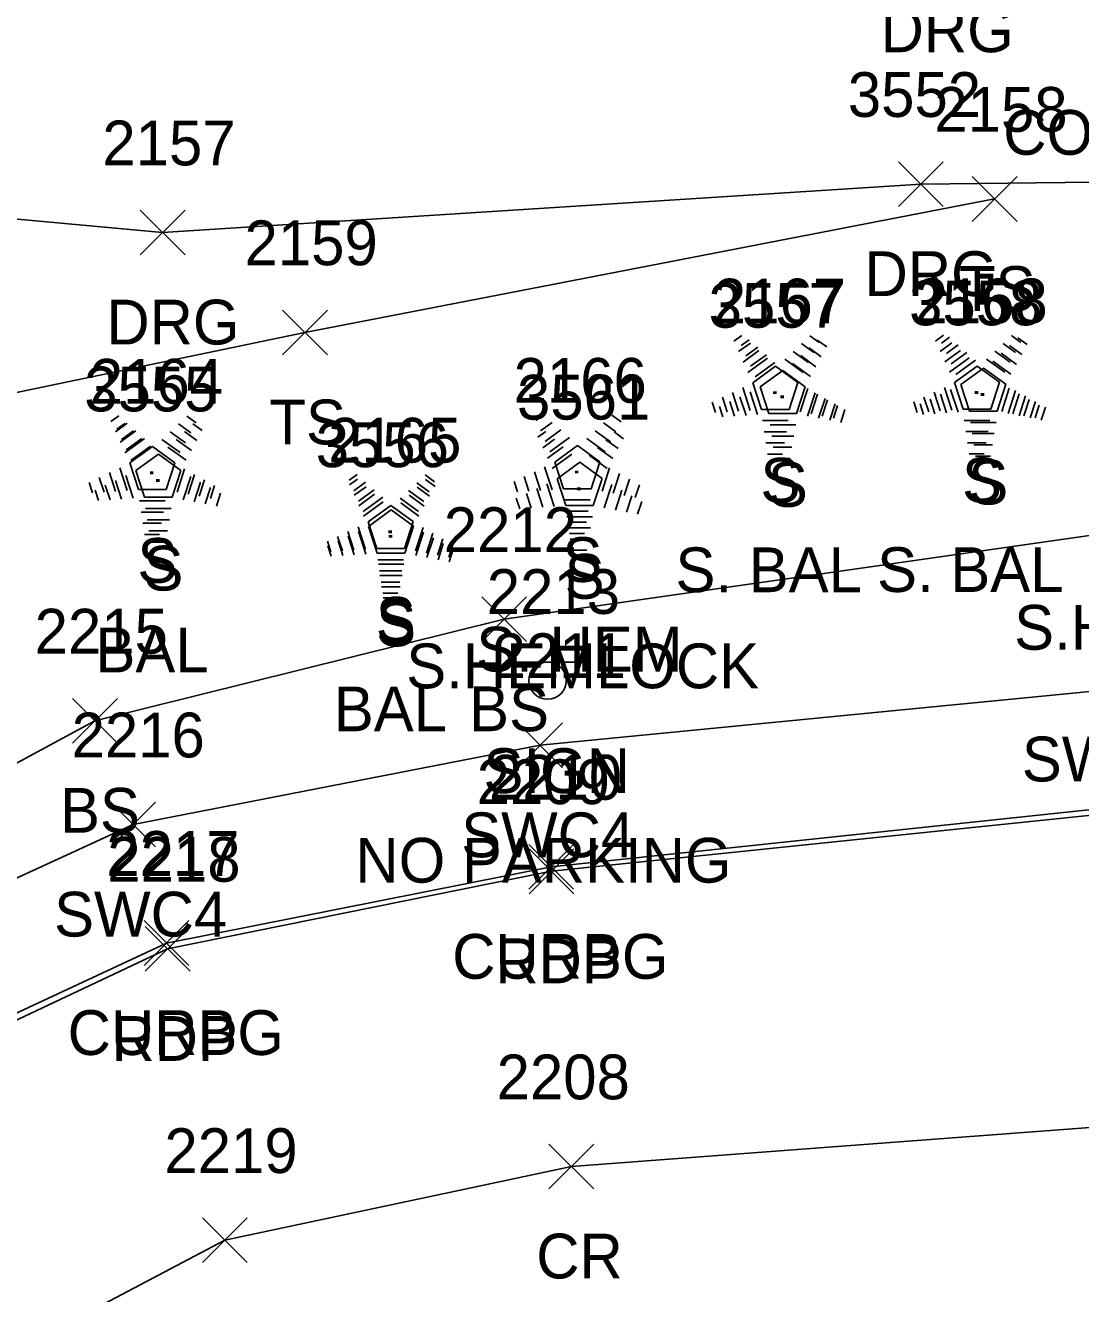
# Model space of a CAD drawing. Extents: x 49137 to 50946, y 9590 to 10709.
# Drawn here: x 50015.9 to 50063, y 10129.9 to 10186.5 of the extents above; entities that cross this region are included whole.
import ezdxf

# ---------------------------------------------------------------- set-up
doc = ezdxf.new("R2010")
doc.units = 0
for name, color, linetype in [('L_A', 7, 'Continuous'), ('L_C', 7, 'Continuous'), ('L_I', 7, 'Continuous'), ('L_TIC', 7, 'Continuous'), ('LELB', 7, 'Continuous'), ('LTC', 7, 'Continuous'), ('P_A', 7, 'Continuous'), ('P_I', 7, 'Continuous'), ('P_TIC', 7, 'Continuous'), ('PET', 7, 'Continuous'), ('PRC', 7, 'Continuous'), ('R_A', 7, 'Continuous'), ('R_I', 7, 'Continuous'), ('R_TIC', 7, 'Continuous'), ('RC', 7, 'Continuous'), ('RDG', 7, 'Continuous'), ('RSW', 7, 'Continuous'), ('S_A', 7, 'Continuous'), ('S_C', 7, 'Continuous'), ('S_I', 7, 'Continuous'), ('SSGN', 7, 'Continuous')]:
    doc.layers.add(name, color=color, linetype=linetype)

msp = doc.modelspace()

# ---------------------------------------------------------------- linework, layer by layer
at = {"layer": 'L_TIC'}
for points in [[(50058.207, 10177.77), (50060.207, 10179.77)], [(50060.207, 10177.77), (50058.207, 10179.77)], [(50027.413, 10171.811), (50029.413, 10173.811)], [(50029.413, 10171.811), (50027.413, 10173.811)], [(50036.302, 10159), (50038.302, 10161)], [(50038.302, 10159), (50036.302, 10161)], [(50018.035, 10154.468), (50020.035, 10156.468)], [(50020.035, 10154.468), (50018.035, 10156.468)]]:
    msp.add_lwpolyline(points, dxfattribs=at)
at = {"layer": 'LELB'}
for points in [[(50059.207, 10178.77), (50028.413, 10172.811), (50009.729, 10168.921), (49990.014, 10158.531), (49982.121, 10132.61), (49968.204, 10108.513), (49962.139, 10093.516), (49959.115, 10077.066), (49958.099, 10070.421), (49954.983, 10070.006), (49949.237, 10070.265), (49946.938, 10062.783)], [(50098.239, 10171.767), (50082.638, 10166.885), (50071.985, 10164.968), (50037.302, 10160), (50019.035, 10155.468), (49996.071, 10143.044), (49982.121, 10132.61), (49977.73, 10134.389), (49971.722, 10123.997), (49967.691, 10108.727), (49960.47, 10094.086), (49957.429, 10077.197), (49956.319, 10072.029), (49954.648, 10071.844), (49954.156, 10074.76), (49955.264, 10079.229)]]:
    msp.add_lwpolyline(points, dxfattribs=at)
at = {"layer": 'LTC'}
for p, q in [((50047.56, 10172.418), (50047.915, 10172.675)), ((50050.959, 10172.658), (50051.378, 10172.353)), ((50056.563, 10172.427), (50056.917, 10172.684)), ((50056.841, 10172.335), (50057.196, 10172.592)), ((50059.961, 10172.667), (50060.38, 10172.363)), ((50060.24, 10172.575), (50060.659, 10172.271)), ((50047.77, 10171.952), (50048.299, 10172.336)), ((50047.891, 10172.229), (50048.245, 10172.486)), ((50047.979, 10171.486), (50048.683, 10171.998)), ((50048.1, 10171.763), (50048.629, 10172.148)), ((50050.216, 10171.961), (50050.896, 10171.468)), ((50050.587, 10172.31), (50051.137, 10171.91)), ((50050.918, 10172.121), (50051.467, 10171.722)), ((50051.289, 10172.469), (50051.708, 10172.165)), ((50056.772, 10171.962), (50057.301, 10172.346)), ((50056.982, 10171.496), (50057.686, 10172.007)), ((50057.051, 10171.87), (50057.58, 10172.254)), ((50059.219, 10171.971), (50059.898, 10171.477)), ((50059.59, 10172.319), (50060.139, 10171.92)), ((50059.869, 10172.227), (50060.418, 10171.828)), ((50048.189, 10171.02), (50049.067, 10171.658)), ((50048.31, 10171.298), (50049.014, 10171.809)), ((50048.519, 10170.832), (50049.398, 10171.47)), ((50049.845, 10171.613), (50050.655, 10171.024)), ((50050.176, 10171.424), (50050.985, 10170.836)), ((50050.547, 10171.773), (50051.226, 10171.279)), ((50057.191, 10171.03), (50058.07, 10171.668)), ((50057.261, 10171.404), (50057.964, 10171.915)), ((50057.47, 10170.938), (50058.349, 10171.576)), ((50058.848, 10171.622), (50059.657, 10171.034)), ((50059.126, 10171.53), (50059.936, 10170.942)), ((50059.498, 10171.879), (50060.177, 10171.385)), ((50048.414, 10170.565), (50049.425, 10171.3)), ((50048.744, 10170.377), (50049.756, 10171.111)), ((50049.425, 10171.3), (50050.422, 10170.575)), ((50049.756, 10171.111), (50050.753, 10170.386)), ((50057.416, 10170.575), (50058.428, 10171.309)), ((50057.695, 10170.483), (50058.706, 10171.217)), ((50058.428, 10171.309), (50059.425, 10170.584)), ((50058.706, 10171.217), (50059.704, 10170.492)), ((50047.959, 10170.346), (50048.29, 10169.327)), ((50048.414, 10170.565), (50048.801, 10169.372)), ((50048.744, 10170.377), (50049.131, 10169.183)), ((50050.422, 10170.575), (50050.031, 10169.372)), ((50050.753, 10170.386), (50050.361, 10169.183)), ((50050.86, 10170.304), (50050.522, 10169.265)), ((50056.961, 10170.356), (50057.292, 10169.337)), ((50057.24, 10170.264), (50057.571, 10169.245)), ((50057.416, 10170.575), (50057.803, 10169.382)), ((50057.695, 10170.483), (50058.082, 10169.29)), ((50059.425, 10170.584), (50059.033, 10169.382)), ((50059.704, 10170.492), (50059.312, 10169.29)), ((50059.862, 10170.314), (50059.524, 10169.274)), ((50046.593, 10169.697), (50046.745, 10169.229)), ((50047.048, 10169.913), (50047.26, 10169.262)), ((50047.379, 10169.725), (50047.59, 10169.073)), ((50047.504, 10170.13), (50047.775, 10169.295)), ((50047.834, 10169.941), (50048.105, 10169.106)), ((50048.289, 10170.158), (50048.62, 10169.138)), ((50051.19, 10170.116), (50050.852, 10169.076)), ((50051.304, 10170.054), (50051.017, 10169.169)), ((50051.635, 10169.865), (50051.347, 10168.981)), ((50051.749, 10169.804), (50051.512, 10169.074)), ((50055.595, 10169.706), (50055.747, 10169.238)), ((50056.051, 10169.923), (50056.262, 10169.271)), ((50056.329, 10169.831), (50056.541, 10169.179)), ((50056.506, 10170.139), (50056.777, 10169.304)), ((50056.785, 10170.047), (50057.056, 10169.212)), ((50060.141, 10170.222), (50059.803, 10169.182)), ((50060.307, 10170.063), (50060.019, 10169.179)), ((50060.586, 10169.971), (50060.298, 10169.087)), ((50060.751, 10169.813), (50060.514, 10169.084)), ((50061.03, 10169.721), (50060.793, 10168.992)), ((50038.715, 10168.874), (50039.07, 10169.132)), ((50042.113, 10169.115), (50042.532, 10168.81)), ((50046.923, 10169.508), (50047.075, 10169.04)), ((50050.031, 10169.372), (50048.801, 10169.372)), ((50050.361, 10169.183), (50049.131, 10169.183)), ((50052.079, 10169.615), (50051.842, 10168.886)), ((50052.193, 10169.553), (50052.006, 10168.979)), ((50052.524, 10169.365), (50052.337, 10168.791)), ((50055.874, 10169.614), (50056.026, 10169.146)), ((50059.033, 10169.382), (50057.803, 10169.382)), ((50059.312, 10169.29), (50058.082, 10169.29)), ((50061.196, 10169.563), (50061.009, 10168.989)), ((50061.474, 10169.471), (50061.288, 10168.897)), ((50019.74, 10168.835), (50020.095, 10169.092)), ((50019.95, 10168.369), (50020.479, 10168.753)), ((50020.01, 10168.492), (50020.365, 10168.749)), ((50022.767, 10168.727), (50023.317, 10168.328)), ((50023.139, 10169.075), (50023.558, 10168.771)), ((50023.409, 10168.732), (50023.828, 10168.427)), ((50038.925, 10168.409), (50039.454, 10168.793)), ((50041.742, 10168.766), (50042.292, 10168.367)), ((50049.993, 10168.872), (50048.848, 10168.872)), ((50050.323, 10168.683), (50049.179, 10168.683)), ((50058.995, 10168.882), (50057.851, 10168.882)), ((50059.274, 10168.79), (50058.129, 10168.79)), ((50020.159, 10167.903), (50020.863, 10168.415)), ((50020.22, 10168.026), (50020.749, 10168.41)), ((50020.369, 10167.438), (50021.247, 10168.076)), ((50020.429, 10167.56), (50021.133, 10168.072)), ((50022.025, 10168.03), (50022.835, 10167.441)), ((50022.397, 10168.378), (50023.076, 10167.885)), ((50022.666, 10168.035), (50023.346, 10167.542)), ((50023.037, 10168.384), (50023.587, 10167.985)), ((50038.816, 10168.126), (50039.171, 10168.384)), ((50039.026, 10167.661), (50039.555, 10168.045)), ((50039.134, 10167.943), (50039.838, 10168.454)), ((50039.344, 10167.477), (50040.222, 10168.115)), ((50041, 10168.07), (50041.81, 10167.481)), ((50041.371, 10168.418), (50042.05, 10167.924)), ((50041.843, 10168.018), (50042.393, 10167.619)), ((50042.215, 10168.367), (50042.634, 10168.062)), ((50049.909, 10168.372), (50048.921, 10168.372)), ((50050.239, 10168.183), (50049.251, 10168.183)), ((50058.911, 10168.382), (50057.923, 10168.382)), ((50059.19, 10168.29), (50058.202, 10168.29)), ((50020.594, 10166.983), (50021.605, 10167.717)), ((50020.639, 10167.095), (50021.517, 10167.732)), ((50021.605, 10167.717), (50022.602, 10166.992)), ((50022.295, 10167.687), (50023.105, 10167.098)), ((50039.236, 10167.195), (50039.939, 10167.706)), ((50039.568, 10167.022), (50040.58, 10167.757)), ((50040.58, 10167.757), (50041.577, 10167.032)), ((50041.473, 10167.67), (50042.152, 10167.176)), ((50049.825, 10167.872), (50048.994, 10167.872)), ((50050.156, 10167.683), (50049.324, 10167.683)), ((50058.828, 10167.882), (50057.996, 10167.882)), ((50059.106, 10167.79), (50058.275, 10167.79)), ((50020.594, 10166.983), (50020.981, 10165.789)), ((50020.864, 10166.64), (50021.875, 10167.374)), ((50021.875, 10167.374), (50022.872, 10166.649)), ((50022.602, 10166.992), (50022.211, 10165.789)), ((50039.445, 10166.729), (50040.323, 10167.367)), ((50039.568, 10167.022), (50039.955, 10165.829)), ((50039.67, 10166.274), (50040.681, 10167.009)), ((50040.681, 10167.009), (50041.678, 10166.284)), ((50041.101, 10167.322), (50041.911, 10166.733)), ((50041.577, 10167.032), (50041.186, 10165.829)), ((50049.741, 10167.372), (50049.066, 10167.372)), ((50050.072, 10167.183), (50049.397, 10167.183)), ((50058.744, 10167.382), (50058.069, 10167.382)), ((50059.023, 10167.29), (50058.348, 10167.29)), ((50019.228, 10166.331), (50019.44, 10165.679)), ((50019.684, 10166.547), (50019.955, 10165.712)), ((50020.139, 10166.763), (50020.47, 10165.744)), ((50020.409, 10166.42), (50020.74, 10165.401)), ((50020.864, 10166.64), (50021.251, 10165.446)), ((50022.872, 10166.649), (50022.481, 10165.446)), ((50023.04, 10166.721), (50022.702, 10165.682)), ((50023.31, 10166.378), (50022.972, 10165.339)), ((50023.484, 10166.471), (50023.197, 10165.586)), ((50030.384, 10166.205), (50030.738, 10166.463)), ((50033.782, 10166.446), (50034.201, 10166.141)), ((50038.203, 10166.37), (50038.415, 10165.719)), ((50038.658, 10166.587), (50038.93, 10165.751)), ((50039.114, 10166.803), (50039.445, 10165.784)), ((50041.678, 10166.284), (50041.287, 10165.081)), ((50042.015, 10166.761), (50041.677, 10165.721)), ((50042.459, 10166.511), (50042.172, 10165.626)), ((50018.773, 10166.114), (50018.925, 10165.646)), ((50019.043, 10165.771), (50019.195, 10165.303)), ((50019.498, 10165.987), (50019.71, 10165.336)), ((50019.954, 10166.204), (50020.225, 10165.369)), ((50022.211, 10165.789), (50020.981, 10165.789)), ((50023.754, 10166.128), (50023.467, 10165.243)), ((50023.929, 10166.221), (50023.692, 10165.491)), ((50024.199, 10165.878), (50023.962, 10165.148)), ((50024.373, 10165.971), (50024.187, 10165.396)), ((50030.401, 10166.001), (50030.756, 10166.258)), ((50030.593, 10165.74), (50031.122, 10166.124)), ((50030.611, 10165.535), (50031.14, 10165.919)), ((50030.803, 10165.274), (50031.506, 10165.785)), ((50033.04, 10165.749), (50033.719, 10165.255)), ((50033.411, 10166.097), (50033.96, 10165.698)), ((50033.429, 10165.893), (50033.978, 10165.494)), ((50033.8, 10166.241), (50034.219, 10165.936)), ((50037.747, 10166.154), (50037.9, 10165.686)), ((50038.76, 10165.839), (50039.031, 10165.003)), ((50039.215, 10166.055), (50039.546, 10165.036)), ((50039.67, 10166.274), (50040.057, 10165.081)), ((50041.186, 10165.829), (50039.955, 10165.829)), ((50042.116, 10166.013), (50041.778, 10164.973)), ((50042.561, 10165.762), (50042.273, 10164.878)), ((50042.904, 10166.261), (50042.667, 10165.531)), ((50043.348, 10166.01), (50043.161, 10165.436)), ((50022.173, 10165.289), (50021.028, 10165.289)), ((50022.481, 10165.446), (50021.251, 10165.446)), ((50024.643, 10165.627), (50024.456, 10165.053)), ((50030.821, 10165.069), (50031.524, 10165.581)), ((50031.012, 10164.808), (50031.891, 10165.446)), ((50031.03, 10164.604), (50031.909, 10165.241)), ((50032.669, 10165.401), (50033.478, 10164.812)), ((50032.686, 10165.196), (50033.496, 10164.607)), ((50033.058, 10165.544), (50033.737, 10165.051)), ((50037.849, 10165.405), (50038.001, 10164.937)), ((50038.304, 10165.622), (50038.516, 10164.97)), ((50041.147, 10165.329), (50040.003, 10165.329)), ((50043.005, 10165.512), (50042.768, 10164.783)), ((50043.449, 10165.262), (50043.263, 10164.688)), ((50022.089, 10164.789), (50021.101, 10164.789)), ((50022.443, 10164.946), (50021.298, 10164.946)), ((50031.237, 10164.353), (50032.249, 10165.088)), ((50031.255, 10164.149), (50032.266, 10164.883)), ((50032.249, 10165.088), (50033.246, 10164.363)), ((50032.266, 10164.883), (50033.264, 10164.158)), ((50041.287, 10165.081), (50040.057, 10165.081)), ((50041.064, 10164.829), (50040.075, 10164.829)), ((50022.005, 10164.289), (50021.174, 10164.289)), ((50022.359, 10164.446), (50021.371, 10164.446)), ((50030.782, 10164.134), (50031.113, 10163.115)), ((50031.237, 10164.353), (50031.624, 10163.16)), ((50031.255, 10164.149), (50031.642, 10162.955)), ((50033.246, 10164.363), (50032.854, 10163.16)), ((50033.264, 10164.158), (50032.872, 10162.955)), ((50033.683, 10164.092), (50033.345, 10163.052)), ((50041.249, 10164.581), (50040.104, 10164.581)), ((50040.98, 10164.329), (50040.148, 10164.329)), ((50041.165, 10164.081), (50040.177, 10164.081)), ((50021.922, 10163.789), (50021.247, 10163.789)), ((50022.275, 10163.946), (50021.444, 10163.946)), ((50029.416, 10163.484), (50029.568, 10163.017)), ((50029.871, 10163.701), (50030.083, 10163.049)), ((50029.889, 10163.496), (50030.101, 10162.845)), ((50030.327, 10163.918), (50030.598, 10163.082)), ((50030.345, 10163.713), (50030.616, 10162.878)), ((50030.8, 10163.929), (50031.131, 10162.91)), ((50033.701, 10163.887), (50033.363, 10162.848)), ((50034.128, 10163.842), (50033.84, 10162.957)), ((50034.146, 10163.637), (50033.858, 10162.752)), ((50034.572, 10163.592), (50034.335, 10162.862)), ((50040.896, 10163.829), (50040.221, 10163.829)), ((50041.081, 10163.581), (50040.25, 10163.581)), ((50022.191, 10163.446), (50021.516, 10163.446)), ((50029.434, 10163.28), (50029.586, 10162.812)), ((50032.854, 10163.16), (50031.624, 10163.16)), ((50032.872, 10162.955), (50031.642, 10162.955)), ((50034.59, 10163.387), (50034.353, 10162.657)), ((50035.016, 10163.341), (50034.83, 10162.767)), ((50035.034, 10163.136), (50034.848, 10162.562)), ((50040.998, 10163.081), (50040.323, 10163.081)), ((50032.816, 10162.66), (50031.671, 10162.66)), ((50032.834, 10162.455), (50031.689, 10162.455)), ((50032.732, 10162.16), (50031.744, 10162.16)), ((50032.75, 10161.955), (50031.762, 10161.955)), ((50032.649, 10161.66), (50031.817, 10161.66)), ((50032.666, 10161.455), (50031.835, 10161.455)), ((50032.565, 10161.16), (50031.89, 10161.16)), ((50032.583, 10160.955), (50031.908, 10160.955))]:
    msp.add_line(p, q, dxfattribs=at)
at = {"layer": 'P_TIC'}
for points in [[(50038.424, 10147.744), (50040.424, 10149.744)], [(50040.424, 10147.744), (50038.424, 10149.744)], [(50021.281, 10144.278), (50023.281, 10146.278)], [(50023.281, 10144.278), (50021.281, 10146.278)], [(50039.307, 10134.561), (50041.307, 10136.561)], [(50041.307, 10134.561), (50039.307, 10136.561)], [(50023.837, 10131.269), (50025.837, 10133.269)], [(50025.837, 10131.269), (50023.837, 10133.269)]]:
    msp.add_lwpolyline(points, dxfattribs=at)
at = {"layer": 'PET'}
msp.add_lwpolyline([(50500, 10146.803), (50482.824, 10146.596), (50451.943, 10142.575), (50406.356, 10149.875), (50391.036, 10152.294), (50366.967, 10154.835), (50332.971, 10157.453), (50281.747, 10161.159), (50239.768, 10163.197), (50191.306, 10163.258), (50147.424, 10160.548), (50119.041, 10158.144), (50090.984, 10156.228), (50087.122, 10154.93), (50074.588, 10152.393), (50039.424, 10148.744), (50022.281, 10145.278), (50001.488, 10135.468), (49981.426, 10116.921), (49974.218, 10104.512), (49968.544, 10090.521), (49966.026, 10076.927), (49965.371, 10068.985)], dxfattribs=at)
at = {"layer": 'PRC'}
msp.add_lwpolyline([(50496.817, 10130.355), (50455.322, 10129.806), (50404.409, 10131.956), (50361.938, 10134.122), (50331.696, 10136.067), (50280.642, 10137.312), (50238.724, 10140.088), (50190.79, 10138.958), (50146.004, 10140.156), (50115.75, 10139.222), (50082.655, 10138.746), (50040.307, 10135.561), (50024.837, 10132.269), (50007.805, 10123.297), (49990.279, 10107.587), (49982.883, 10090.76), (49978.98, 10075.387)], dxfattribs=at)
at = {"layer": 'R_TIC'}
for points in [[(50054.91, 10178.434), (50056.91, 10180.434)], [(50056.91, 10178.434), (50054.91, 10180.434)], [(50021.058, 10176.271), (50023.058, 10178.271)], [(50023.058, 10176.271), (50021.058, 10178.271)], [(50037.915, 10153.372), (50039.915, 10155.372)], [(50039.915, 10153.372), (50037.915, 10155.372)], [(50019.739, 10149.83), (50021.739, 10151.83)], [(50021.739, 10149.83), (50019.739, 10151.83)], [(50038.404, 10147.944), (50040.404, 10149.944)], [(50040.404, 10147.944), (50038.404, 10149.944)], [(50021.233, 10144.541), (50023.233, 10146.541)], [(50023.233, 10144.541), (50021.233, 10146.541)]]:
    msp.add_lwpolyline(points, dxfattribs=at)
at = {"layer": 'RC'}
msp.add_lwpolyline([(50090.984, 10156.228), (50086.802, 10155.012), (50074.635, 10152.68), (50039.404, 10148.944), (50022.233, 10145.541), (50001.273, 10135.771), (49981.184, 10117.18), (49973.858, 10104.886), (49968.286, 10090.59), (49965.755, 10076.904), (49965.095, 10068.882)], dxfattribs=at)
at = {"layer": 'RDG'}
for points in [[(50039.942, 10195.24), (50008.077, 10193.664), (50008.455, 10178.516), (50022.058, 10177.271)], [(50022.058, 10177.271), (50055.91, 10179.434)], [(50068.798, 10179.582), (50055.91, 10179.434)]]:
    msp.add_lwpolyline(points, dxfattribs=at)
at = {"layer": 'RSW'}
msp.add_lwpolyline([(50073.539, 10157.759), (50038.915, 10154.372), (50020.739, 10150.83), (49998.164, 10140.457), (49976.714, 10120.181), (49969.231, 10107.368), (49963.065, 10092.754), (49960.301, 10076.5)], dxfattribs=at)
at = {"layer": 'SSGN'}
for p, q in [((50037.597, 10158.091), (50040.93, 10158.091)), ((50039.244, 10157.258), (50039.244, 10157.258))]:
    msp.add_line(p, q, dxfattribs=at)
msp.add_circle((50039.244, 10157.258), 0.833, dxfattribs=at)

# ---------------------------------------------------------------- texts
at = {"layer": 'L_A'}
for s, p in [('TS', (50057.616, 10173.77)), ('TS', (50026.823, 10167.811)), ('S', (50048.751, 10165.209)), ('S', (50049.081, 10165.021)), ('S', (50057.753, 10165.219)), ('S', (50058.032, 10165.127)), ('S', (50020.931, 10161.627)), ('S', (50039.906, 10161.666)), ('S', (50021.201, 10161.283)), ('S', (50040.007, 10160.918)), ('S', (50031.574, 10158.997)), ('S', (50031.592, 10158.792)), ('BS', (50035.743, 10155)), ('BS', (50017.476, 10150.468))]:
    msp.add_text(s, height=2, dxfattribs=at).set_placement(p)
at = {"layer": 'L_C'}
for s, p in [('CONC. BLOCKS', (50059.592, 10180.743)), ('S. BAL', (50044.956, 10161.209)), ('S. BAL', (50053.958, 10161.219)), ('S.HEMLOCK', (50060.077, 10158.641)), ('BAL', (50019.057, 10157.627)), ('S. HEM', (50036.063, 10157.666)), ('S.HEMLOCK', (50032.936, 10156.918)), ('BAL', (50029.7, 10154.997))]:
    msp.add_text(s, height=2, dxfattribs=at).set_placement(p)
at = {"layer": 'L_I'}
for s, p in [('2158', (50056.514, 10181.77)), ('2159', (50025.713, 10175.811)), ('3557', (50046.436, 10173.021)), ('2167', (50046.625, 10173.209)), ('3558', (50055.387, 10173.127)), ('2168', (50055.628, 10173.219)), ('2164', (50018.805, 10169.627)), ('2166', (50037.725, 10169.666)), ('3555', (50018.555, 10169.283)), ('3561', (50037.881, 10168.918)), ('3556', (50028.891, 10166.792)), ('2165', (50029.448, 10166.997)), ('2212', (50034.61, 10163)), ('2215', (50016.342, 10158.468))]:
    msp.add_text(s, height=2, dxfattribs=at).set_placement(p)
at = {"layer": 'LTC'}
for p in [(50049.308, 10170.313), (50049.638, 10170.125), (50058.31, 10170.323), (50058.589, 10170.231), (50021.488, 10166.731), (50040.462, 10166.77), (50021.758, 10166.387), (50040.564, 10166.022), (50032.131, 10164.101), (50032.149, 10163.896)]:
    msp.add_text('.', height=1.037, rotation=270, dxfattribs=at).set_placement(p)
at = {"layer": 'P_A'}
for s, p in [('RDP', (50036.912, 10143.744)), ('RDP', (50019.769, 10140.278)), ('CR', (50038.74, 10130.561))]:
    msp.add_text(s, height=2, dxfattribs=at).set_placement(p)
at = {"layer": 'P_I'}
for s, p in [('2209', (50036.078, 10151.744)), ('2218', (50019.588, 10148.278)), ('2208', (50036.969, 10138.561)), ('2219', (50022.136, 10135.269))]:
    msp.add_text(s, height=2, dxfattribs=at).set_placement(p)
at = {"layer": 'R_A'}
for s, p in [('DRG', (50054.114, 10185.323)), ('DRG', (50053.398, 10174.434)), ('DRG', (50019.546, 10172.271)), ('SWC4 ST JT 3541', (50060.421, 10152.759)), ('SWC4', (50035.388, 10149.372)), ('SWC4', (50017.212, 10145.83)), ('CURBG', (50034.986, 10143.944)), ('CURBG', (50017.816, 10140.541))]:
    msp.add_text(s, height=2, dxfattribs=at).set_placement(p)
at = {"layer": 'R_I'}
for s, p in [('3552', (50052.651, 10182.434)), ('2157', (50019.365, 10180.271)), ('2211', (50036.79, 10157.372)), ('2216', (50017.991, 10153.83)), ('2210', (50036.624, 10151.944)), ('2217', (50019.54, 10148.541))]:
    msp.add_text(s, height=2, dxfattribs=at).set_placement(p)
at = {"layer": 'S_A'}
msp.add_text('SIGN', height=2, dxfattribs=at).set_placement((50036.382, 10152.238))
at = {"layer": 'S_C'}
msp.add_text('NO PARKING', height=2, dxfattribs=at).set_placement((50030.666, 10148.238))
at = {"layer": 'S_I'}
msp.add_text('2213', height=2, dxfattribs=at).set_placement((50036.532, 10160.238))

doc.saveas('drawing.dxf')
